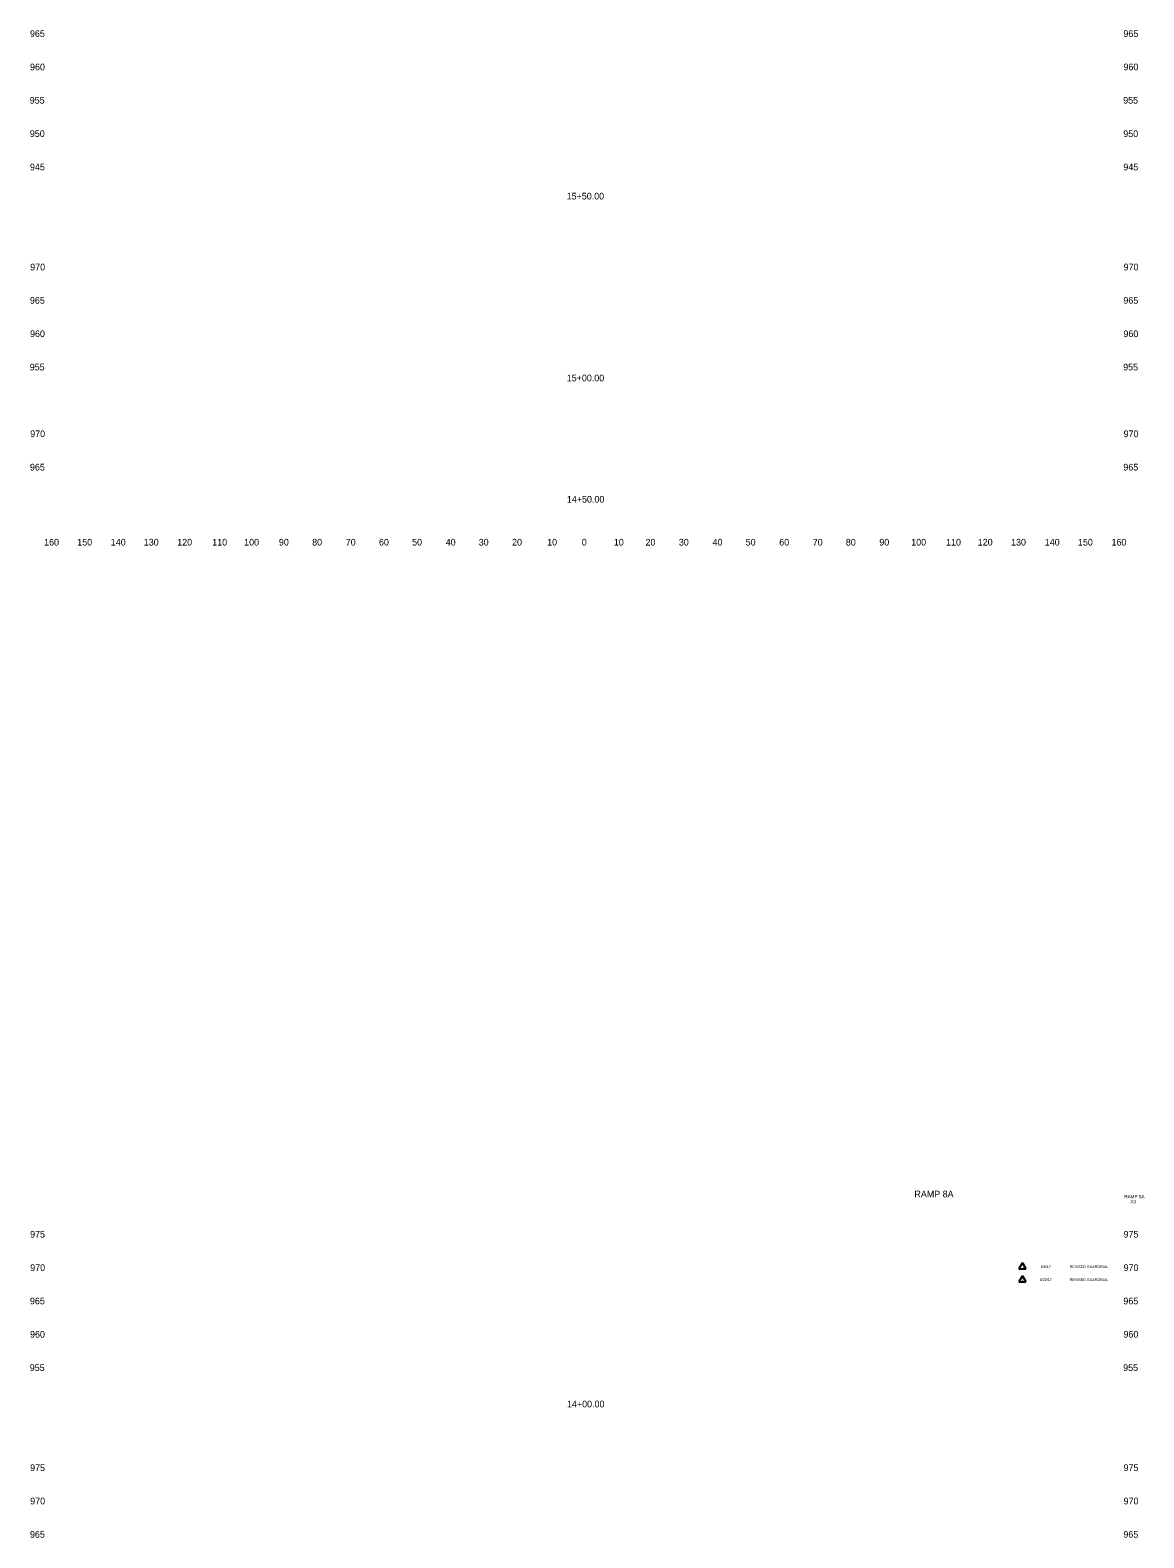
# Model space of a CAD drawing. Extents: x 4994 to 5328, y 4997 to 8804.
# Drawn here: x 4993.9 to 5327.8, y 5900 to 6352 of the extents above; entities that cross this region are included whole.
import ezdxf

# ---------------------------------------------------------------- set-up
doc = ezdxf.new("R2010")
doc.units = 0
for name, color, linetype in [('RD_SHT_ID', 7, 'Continuous'), ('RD_SHT_TX', 7, 'Continuous'), ('RD_XS_TX_Offset', 7, 'Continuous'), ('RD_XS_TX_Station', 7, 'Continuous')]:
    doc.layers.add(name, color=color, linetype=linetype)

msp = doc.modelspace()

# ---------------------------------------------------------------- linework, layer by layer
at = {"layer": 'RD_SHT_TX'}
for p, q in [((5291.4, 5982.45), (5290.37, 5980.62)), ((5291.4, 5982.45), (5292.42, 5980.62)), ((5290.37, 5980.62), (5292.42, 5980.62)), ((5291.4, 5978.56), (5290.37, 5976.73)), ((5290.37, 5976.73), (5292.42, 5976.73)), ((5291.4, 5978.56), (5292.42, 5976.73))]:
    msp.add_line(p, q, dxfattribs=at)

# ---------------------------------------------------------------- texts
at = {"layer": 'RD_SHT_ID'}
for s, height, p in [('RAMP 8A', 2, (5259.02, 6002.06)), ('RAMP 8A', 1, (5321.93, 6001.8)), ('X3', 1, (5323.74, 6000.3))]:
    msp.add_text(s, height=height, dxfattribs=at).set_placement(p)
at = {"layer": 'RD_SHT_TX'}
for s, p in [('1', (5291.4, 5980.91)), ('6/6/17', (5296.9, 5980.88)), ('REVISED GUARDRAIL', (5305.6, 5980.88)), ('2', (5291.17, 5977.02)), ('6/23/17', (5296.56, 5976.99)), ('REVISED GUARDRAIL', (5305.6, 5976.99))]:
    msp.add_text(s, height=0.792, dxfattribs=at).set_placement(p)
at = {"layer": 'RD_XS_TX_Offset'}
for s, p in [('965', (4993.86, 6350)), ('965', (5321.66, 6350)), ('960', (4993.89, 6340)), ('960', (5321.69, 6340)), ('955', (4993.8, 6330)), ('955', (5321.6, 6330)), ('950', (4993.83, 6320)), ('950', (5321.63, 6320)), ('945', (4993.86, 6310)), ('945', (5321.66, 6310)), ('970', (4993.94, 6280)), ('970', (5321.74, 6280)), ('965', (4993.86, 6270)), ('965', (5321.66, 6270)), ('960', (4993.89, 6260)), ('960', (5321.69, 6260)), ('955', (4993.8, 6250)), ('955', (5321.6, 6250)), ('970', (4993.94, 6230)), ('970', (5321.74, 6230)), ('965', (4993.86, 6220)), ('965', (5321.66, 6220)), ('160', (4998.1, 6197.5)), ('150', (5008.04, 6197.5)), ('140', (5018.1, 6197.5)), ('130', (5027.99, 6197.5)), ('120', (5038.01, 6197.5)), ('110', (5048.51, 6197.5)), ('100', (5058.07, 6197.5)), ('90', (5068.5, 6197.5)), ('80', (5078.46, 6197.5)), ('70', (5088.54, 6197.5)), ('60', (5098.5, 6197.5)), ('50', (5108.43, 6197.5)), ('40', (5118.5, 6197.5)), ('30', (5128.39, 6197.5)), ('20', (5138.4, 6197.5)), ('10', (5148.91, 6197.5)), ('0', (5159.3, 6197.5)), ('0', (5159.3, 6197.5)), ('10', (5168.91, 6197.5)), ('20', (5178.4, 6197.5)), ('30', (5188.39, 6197.5)), ('40', (5198.5, 6197.5)), ('50', (5208.43, 6197.5)), ('60', (5218.5, 6197.5)), ('70', (5228.54, 6197.5)), ('80', (5238.46, 6197.5)), ('90', (5248.5, 6197.5)), ('100', (5258.07, 6197.5)), ('110', (5268.51, 6197.5)), ('120', (5278.01, 6197.5)), ('130', (5287.99, 6197.5)), ('140', (5298.1, 6197.5)), ('150', (5308.04, 6197.5)), ('160', (5318.1, 6197.5)), ('975', (4993.91, 5990)), ('975', (5321.71, 5990)), ('970', (4993.94, 5980)), ('970', (5321.74, 5980)), ('965', (4993.86, 5970)), ('965', (5321.66, 5970)), ('960', (4993.89, 5960)), ('960', (5321.69, 5960)), ('955', (4993.8, 5950)), ('955', (5321.6, 5950)), ('975', (4993.91, 5920)), ('975', (5321.71, 5920)), ('970', (4993.94, 5910)), ('970', (5321.74, 5910)), ('965', (4993.86, 5900)), ('965', (5321.66, 5900))]:
    msp.add_text(s, height=2, dxfattribs=at).set_placement(p)
at = {"layer": 'RD_XS_TX_Station'}
for s, p in [('15+50.00', (5154.76, 6301.26)), ('15+00.00', (5154.8, 6246.74)), ('14+50.00', (5154.83, 6210.37)), ('14+00.00', (5154.86, 5939.08))]:
    msp.add_text(s, height=2, dxfattribs=at).set_placement(p)

doc.saveas('drawing.dxf')
